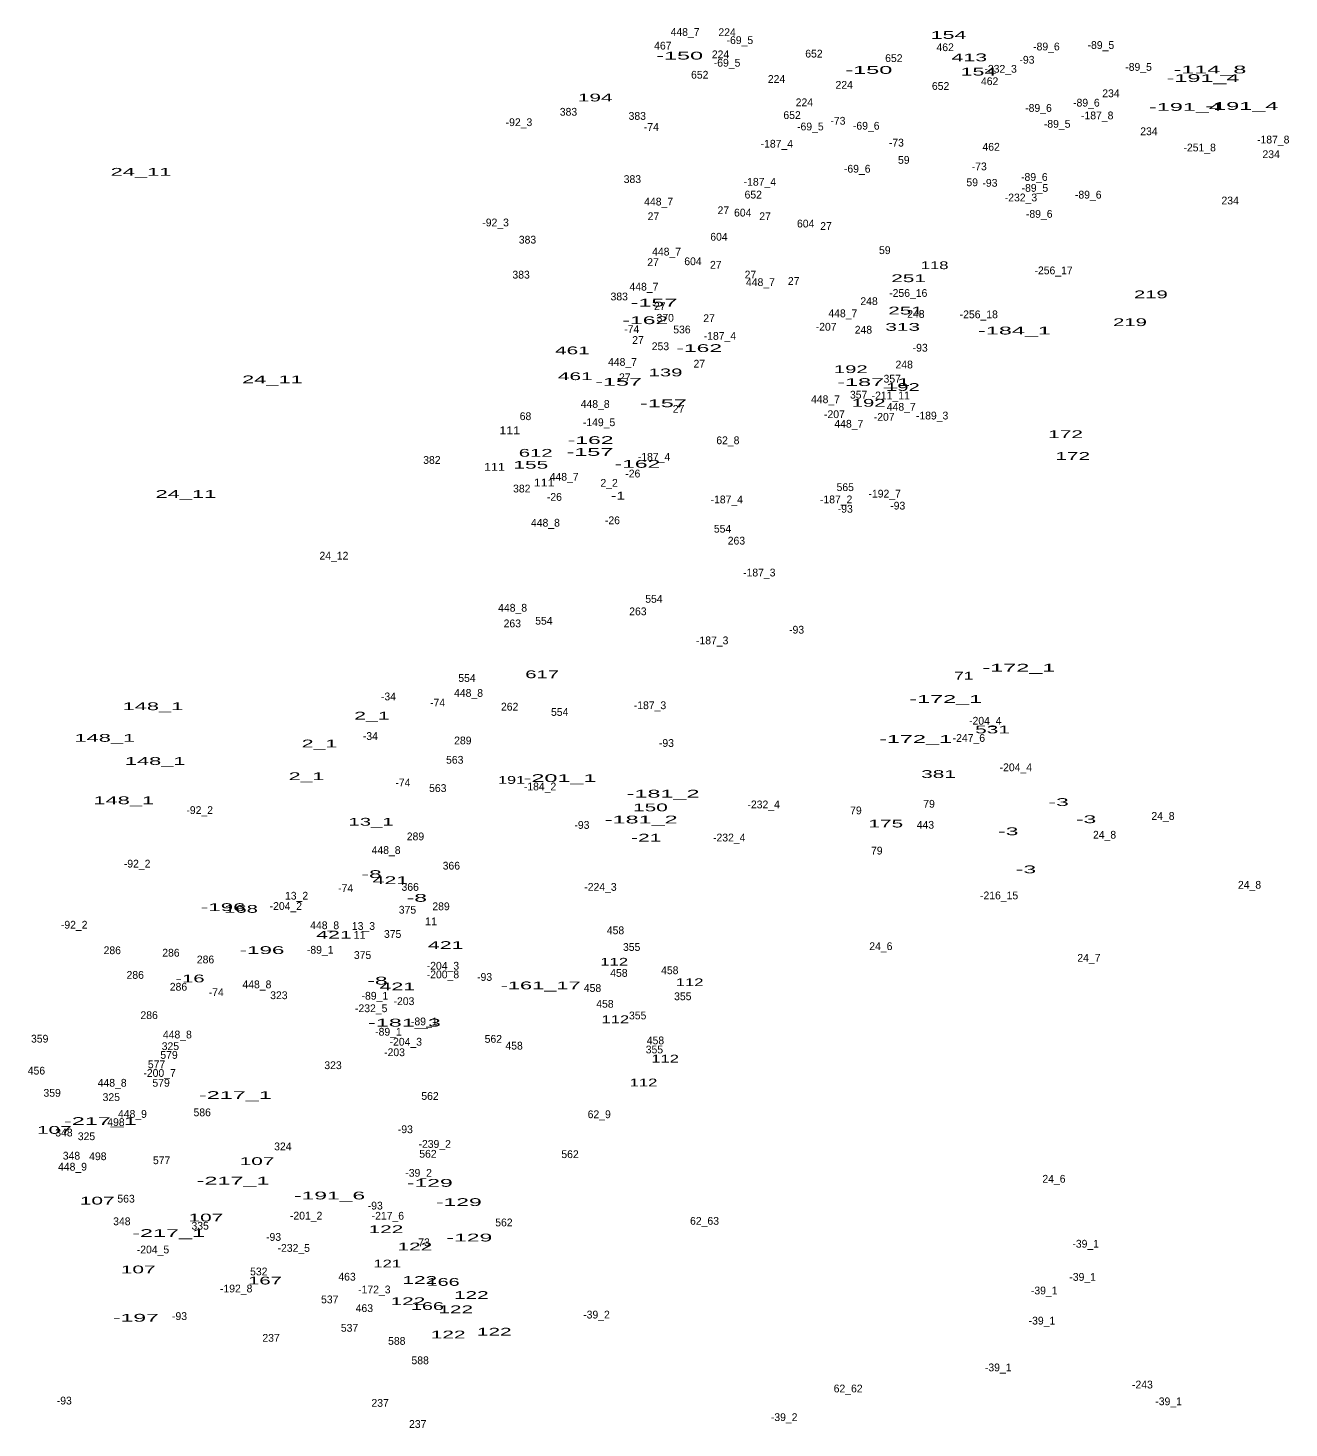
# Model space of a CAD drawing. Extents: x -661742 to -657295, y -1002932 to -996888.
# Drawn here: x -660431 to -659782, y -1001400 to -1000680 of the extents above; entities that cross this region are included whole.
import ezdxf
from ezdxf.enums import TextEntityAlignment as Align

# ---------------------------------------------------------------- set-up
doc = ezdxf.new("R2010")
doc.units = 0
doc.header["$LTSCALE"] = 1.6
doc.layers.add('24', color=7, linetype='Continuous')

msp = doc.modelspace()

# ---------------------------------------------------------------- texts
at = {"layer": '24'}
for s, p in [('448_7', (-660092.849, -1000684.01)), ('224', (-660071.231, -1000684.11)), ('467', (-660104.283, -1000691.03)), ('-69_5', (-660064.653, -1000688.2)), ('462', (-659959.067, -1000691.86)), ('-89_6', (-659906.993, -1000691.47)), ('-89_5', (-659878.978, -1000690.72)), ('224', (-660074.621, -1000695.52)), ('652', (-660026.563, -1000695.14)), ('652', (-659985.463, -1000697.45)), ('-93', (-659916.99, -1000698.3)), ('652', (-660085.303, -1000706)), ('-69_5', (-660071.243, -1000699.84)), ('-232_3', (-659930.532, -1000702.95)), ('-89_5', (-659859.588, -1000701.97)), ('224', (-660045.801, -1000708.19)), ('224', (-660010.991, -1000711.19)), ('652', (-659961.423, -1000711.8)), ('462', (-659936.187, -1000709.32)), ('224', (-660031.491, -1000720.19)), ('-89_6', (-659886.443, -1000720.36)), ('234', (-659873.791, -1000715.54)), ('383', (-660152.807, -1000725.05)), ('383', (-660117.417, -1000727.18)), ('652', (-660037.803, -1000726.75)), ('-89_6', (-659911.063, -1000723.08)), ('-187_8', (-659880.862, -1000726.93)), ('-92_3', (-660178.268, -1000730.4)), ('-74', (-660110.195, -1000732.89)), ('-69_5', (-660028.403, -1000732.62)), ('-73', (-660014.211, -1000729.68)), ('-69_6', (-659999.648, -1000732.23)), ('-89_5', (-659901.468, -1000731.25)), ('234', (-659854.261, -1000735.08)), ('-187_4', (-660045.646, -1000741.48)), ('-73', (-659984.171, -1000740.92)), ('-187_8', (-659790.322, -1000739.34)), ('59', (-659980.353, -1000749.8)), ('462', (-659935.417, -1000743.06)), ('-251_8', (-659828.156, -1000743.42)), ('234', (-659791.411, -1000746.88)), ('-69_6', (-660004.298, -1000754.34)), ('-73', (-659941.531, -1000753.14)), ('383', (-660119.937, -1000759.68)), ('-187_4', (-660054.366, -1000761.07)), ('59', (-659945.153, -1000761.31)), ('-93', (-659936.03, -1000761.61)), ('-89_6', (-659913.203, -1000758.57)), ('-89_5', (-659912.908, -1000764.2)), ('448_7', (-660106.429, -1000771.24)), ('652', (-660057.773, -1000767.66)), ('-232_3', (-659920.082, -1000769.12)), ('-89_6', (-659885.473, -1000767.68)), ('234', (-659812.491, -1000770.68)), ('27', (-660073.153, -1000775.7)), ('604', (-660063.191, -1000776.92)), ('-89_6', (-659910.683, -1000777.57)), ('-92_3', (-660190.288, -1000781.98)), ('27', (-660109.123, -1000778.79)), ('27', (-660051.683, -1000778.79)), ('604', (-660030.811, -1000782.55)), ('27', (-660020.353, -1000783.82)), ('383', (-660173.887, -1000790.83)), ('604', (-660075.401, -1000789.33)), ('448_7', (-660102.349, -1000796.98)), ('59', (-659990.113, -1000796.23)), ('27', (-660109.313, -1000802.4)), ('604', (-660088.781, -1000801.94)), ('27', (-660077.023, -1000803.75)), ('-256_17', (-659903.306, -1000806.63)), ('383', (-660177.177, -1000808.83)), ('27', (-660059.223, -1000808.78)), ('448_7', (-660054.079, -1000812.69)), ('27', (-660036.983, -1000812.07)), ('383', (-660126.707, -1000820.05)), ('448_7', (-660113.989, -1000815.02)), ('-256_16', (-659978.046, -1000818.26)), ('27', (-660105.833, -1000825.03)), ('448_7', (-660011.699, -1000828.71)), ('248', (-659998.211, -1000822.45)), ('370', (-660103.057, -1000831.02)), ('27', (-660080.503, -1000831.22)), ('-207', (-660020.284, -1000835.62)), ('248', (-659974.131, -1000829.03)), ('-256_18', (-659941.781, -1000829.25)), ('-74', (-660120.275, -1000836.84)), ('27', (-660117.053, -1000842.44)), ('536', (-660094.443, -1000837.03)), ('-187_4', (-660074.916, -1000840.32)), ('248', (-660001.111, -1000837.15)), ('253', (-660105.517, -1000845.66)), ('-93', (-659971.91, -1000846.41)), ('448_7', (-660125.019, -1000853.73)), ('27', (-660085.523, -1000854.63)), ('248', (-659980.131, -1000855.05)), ('27', (-660123.823, -1000861.6)), ('357', (-659986.303, -1000862.35)), ('357', (-660003.563, -1000870.56)), ('-211_11', (-659987.07, -1000870.97)), ('448_8', (-660139.074, -1000875.34)), ('27', (-660096.163, -1000877.85)), ('448_7', (-660020.619, -1000872.93)), ('448_7', (-659981.649, -1000876.81)), ('68', (-660174.913, -1000881.63)), ('-149_5', (-660137.076, -1000884.74)), ('-207', (-660016.014, -1000880.61)), ('448_7', (-660008.599, -1000885.53)), ('-207', (-659990.424, -1000881.97)), ('-189_3', (-659965.782, -1000881.31)), ('62_8', (-660070.82, -1000894.03)), ('382', (-660223.057, -1000904.15)), ('-187_4', (-660108.806, -1000902.53)), ('448_7', (-660155.029, -1000912.8)), ('-26', (-660119.72, -1000911.13)), ('382', (-660176.827, -1000918.85)), ('2_2', (-660131.896, -1000915.92)), ('565', (-660010.463, -1000918.14)), ('-192_7', (-659990.187, -1000921.46)), ('-26', (-660160.05, -1000923.15)), ('-187_4', (-660071.386, -1000924.44)), ('-187_2', (-660015.132, -1000924.43)), ('-93', (-660010.45, -1000929.26)), ('-93', (-659983.46, -1000927.64)), ('448_8', (-660164.664, -1000936.43)), ('-26', (-660130.19, -1000935.17)), ('554', (-660073.561, -1000939.51)), ('263', (-660066.433, -1000945.65)), ('24_12', (-660273.453, -1000953.38)), ('-187_3', (-660054.662, -1000962.05)), ('448_8', (-660181.534, -1000980.16)), ('554', (-660108.851, -1000975.59)), ('554', (-660165.461, -1000986.84)), ('263', (-660117.103, -1000982.02)), ('263', (-660181.693, -1000988.21)), ('-93', (-660035.47, -1000991.45)), ('-187_3', (-660078.892, -1000996.95)), ('554', (-660205.001, -1001016.31)), ('-34', (-660245.399, -1001025.78)), ('-74', (-660220.125, -1001028.94)), ('448_8', (-660204.214, -1001023.99)), ('-187_3', (-660110.882, -1001030.31)), ('262', (-660183.053, -1001031.04)), ('554', (-660157.311, -1001033.77)), ('-204_4', (-659938.435, -1001038.29)), ('-34', (-660254.699, -1001046.15)), ('289', (-660207.143, -1001048.42)), ('-93', (-660102.43, -1001049.75)), ('-247_6', (-659946.878, -1001047.13)), ('563', (-660211.293, -1001058.37)), ('-204_4', (-659922.725, -1001062.24)), ('-74', (-660237.955, -1001070.05)), ('563', (-660220.023, -1001072.92)), ('-184_2', (-660167.43, -1001072.08)), ('79', (-659967.348, -1001081)), ('-92_2', (-660342.478, -1001084.25)), ('-232_4', (-660052.427, -1001081.33)), ('79', (-660004.958, -1001084.39)), ('24_8', (-659847.04, -1001087.26)), ('-93', (-660145.88, -1001091.87)), ('443', (-659969.226, -1001091.81)), ('289', (-660231.513, -1001097.76)), ('-232_4', (-660070.127, -1001098.36)), ('24_8', (-659877.08, -1001096.92)), ('448_8', (-660246.614, -1001104.8)), ('79', (-659994.228, -1001105.09)), ('-92_2', (-660374.658, -1001111.79)), ('366', (-660213.038, -1001112.83)), ('366', (-660234.218, -1001123.76)), ('-224_3', (-660136.357, -1001123.76)), ('24_8', (-659802.52, -1001122.67)), ('13_2', (-660292.649, -1001128.28)), ('-74', (-660267.425, -1001124.35)), ('-216_15', (-659931.335, -1001128.13)), ('-204_2', (-660298.181, -1001133.59)), ('375', (-660235.613, -1001135.49)), ('289', (-660218.353, -1001133.74)), ('-92_2', (-660407.038, -1001143.21)), ('448_8', (-660278.214, -1001143.48)), ('13_3', (-660258.259, -1001143.85)), ('375', (-660243.243, -1001147.96)), ('458', (-660128.621, -1001146.08)), ('286', (-660387.433, -1001156.34)), ('286', (-660357.263, -1001157.6)), ('-89_1', (-660280.492, -1001156.08)), ('375', (-660258.723, -1001158.8)), ('355', (-660120.307, -1001154.66)), ('24_6', (-659992.134, -1001154.24)), ('24_7', (-659885.135, -1001160.23)), ('286', (-660339.473, -1001161.08)), ('-204_3', (-660217.391, -1001164.31)), ('458', (-660100.701, -1001166.63)), ('286', (-660375.633, -1001169.02)), ('448_8', (-660313.054, -1001173.88)), ('-200_8', (-660217.37, -1001168.76)), ('-93', (-660195.95, -1001170.07)), ('458', (-660126.871, -1001167.99)), ('286', (-660353.393, -1001175.11)), ('-74', (-660333.965, -1001177.91)), ('323', (-660301.757, -1001179.47)), ('-89_1', (-660252.382, -1001179.74)), ('458', (-660140.441, -1001175.75)), ('355', (-660094.007, -1001180.01)), ('-232_5', (-660254.272, -1001186.17)), ('-203', (-660237.419, -1001182.52)), ('458', (-660134.051, -1001183.89)), ('286', (-660368.483, -1001189.72)), ('-89_1', (-660226.982, -1001192.93)), ('355', (-660117.217, -1001189.87)), ('359', (-660424.763, -1001201.82)), ('448_8', (-660353.964, -1001199.68)), ('-89_1', (-660245.402, -1001198.26)), ('-204_3', (-660236.481, -1001203.39)), ('562', (-660191.453, -1001201.92)), ('458', (-660108.071, -1001202.71)), ('579', (-660358.258, -1001210.17)), ('325', (-660357.547, -1001205.66)), ('-203', (-660242.269, -1001208.8)), ('458', (-660180.771, -1001205.42)), ('355', (-660108.607, -1001207.38)), ('577', (-660364.679, -1001215)), ('323', (-660273.907, -1001215.46)), ('456', (-660426.447, -1001218.25)), ('448_8', (-660387.504, -1001224.5)), ('-200_7', (-660363.106, -1001219.46)), ('579', (-660362.328, -1001224.51)), ('359', (-660418.373, -1001229.68)), ('325', (-660387.947, -1001231.88)), ('562', (-660224.023, -1001231.28)), ('498', (-660385.557, -1001244.74)), ('448_9', (-660377.069, -1001240.52)), ('586', (-660341.183, -1001239.71)), ('62_9', (-660136.986, -1001240.7)), ('348', (-660412.301, -1001250.1)), ('325', (-660400.717, -1001252)), ('-93', (-660236.71, -1001248.41)), ('324', (-660299.721, -1001257.23)), ('-239_2', (-660221.608, -1001255.95)), ('562', (-660225.083, -1001261.03)), ('448_9', (-660407.899, -1001267.67)), ('348', (-660408.431, -1001262.01)), ('498', (-660394.867, -1001262.3)), ('577', (-660362.059, -1001264.35)), ('562', (-660152.003, -1001261.23)), ('-39_2', (-660229.888, -1001270.82)), ('24_6', (-659903.104, -1001273.89)), ('563', (-660380.343, -1001284.11)), ('-93', (-660252.18, -1001287.69)), ('348', (-660382.521, -1001295.76)), ('-201_2', (-660287.74, -1001292.84)), ('-217_6', (-660245.707, -1001292.91)), ('562', (-660186.023, -1001296.33)), ('62_63', (-660082.826, -1001295.53)), ('335', (-660342.247, -1001298.03)), ('-93', (-660304.48, -1001303.79)), ('-204_5', (-660366.491, -1001310.26)), ('-232_5', (-660294.112, -1001309.45)), ('73', (-660227.093, -1001306.55)), ('-39_1', (-659886.802, -1001307.29)), ('532', (-660312.087, -1001321.56)), ('463', (-660266.697, -1001324.24)), ('-39_1', (-659888.362, -1001324.35)), ('-192_8', (-660323.712, -1001330.33)), ('-172_3', (-660252.652, -1001330.81)), ('-39_1', (-659908.132, -1001331.34)), ('537', (-660275.603, -1001335.92)), ('-93', (-660352.85, -1001344.51)), ('463', (-660257.787, -1001340.41)), ('-39_2', (-660138.388, -1001343.74)), ('-39_1', (-659909.292, -1001346.85)), ('537', (-660265.423, -1001350.56)), ('237', (-660305.773, -1001355.7)), ('588', (-660241.107, -1001357.27)), ('588', (-660229.087, -1001367.26)), ('-39_1', (-659931.782, -1001370.9)), ('62_62', (-660008.966, -1001381.75)), ('-243', (-659857.609, -1001379.73)), ('-93', (-660412.12, -1001387.97)), ('237', (-660249.683, -1001389.17)), ('-39_1', (-659844.152, -1001388.35)), ('-39_2', (-660041.878, -1001396.49)), ('237', (-660230.343, -1001400.01))]:
    msp.add_text(s, height=4, dxfattribs=at).set_placement(p, align=Align.CENTER)
for s, width, p in [('154', 2.05, (-659957.333, -1000685.53)), ('-150', 2.25, (-660095.627, -1000696.17)), ('413', 2.05, (-659946.643, -1000697.07)), ('-150', 2.25, (-659998.307, -1000703.54)), ('154', 2.05, (-659941.953, -1000704.4)), ('-114_8', 2.25, (-659822.903, -1000703.3)), ('-191_4', 2.25, (-659826.458, -1000707.71)), ('194', 2, (-660139.068, -1000717.72)), ('-191_4', 2.25, (-659835.478, -1000722.55)), ('-191_4', 2.25, (-659806.488, -1000722.06)), ('24_11', 2.1, (-660372.651, -1000755.93)), ('118', 1.6, (-659964.494, -1000803.99)), ('251', 2, (-659977.867, -1000810.66)), ('219', 1.95, (-659853.273, -1000818.97)), ('-157', 2.25, (-660108.815, -1000823.22)), ('251', 2, (-659979.417, -1000827.3)), ('-162', 2.2, (-660113.295, -1000832.26)), ('313', 2, (-659980.917, -1000835.69)), ('219', 1.95, (-659864.003, -1000833.27)), ('-184_1', 2.25, (-659923.413, -1000837.57)), ('461', 2, (-660150.768, -1000847.78)), ('-162', 2.2, (-660085.575, -1000846.61)), ('192', 1.95, (-660007.613, -1000857.44)), ('24_11', 2.1, (-660305.071, -1000862.71)), ('461', 2, (-660149.318, -1000861.05)), ('-157', 2.25, (-660127.045, -1000863.94)), ('139', 1.95, (-660102.893, -1000859.11)), ('-187_1', 2.25, (-659995.833, -1000864.08)), ('192', 1.95, (-659980.833, -1000866.63)), ('-157', 2.25, (-660103.975, -1000875)), ('192', 1.95, (-659998.433, -1000874.75)), ('111', 1.2, (-660183.03, -1000888.89)), ('172', 2, (-659897.133, -1000890.88)), ('612', 1.95, (-660169.663, -1000900.47)), ('-157', 2.25, (-660141.775, -1000900.02)), ('-162', 2.2, (-660141.405, -1000893.93)), ('111', 1.2, (-660190.87, -1000907.66)), ('155', 2, (-660172.167, -1000906.62)), ('-162', 2.2, (-660117.365, -1000906.15)), ('172', 2, (-659893.463, -1000902.1)), ('24_11', 2.1, (-660349.591, -1000921.66)), ('111', 1.2, (-660165.34, -1000915.78)), ('-1', 1.55, (-660127.281, -1000922.52)), ('617', 1.95, (-660166.337, -1001014.38)), ('71', 1.65, (-659949.483, -1001015.11)), ('-172_1', 2.25, (-659921.163, -1001011)), ('-172_1', 2.25, (-659958.773, -1001027.1)), ('148_1', 2.1, (-660366.541, -1001030.83)), ('2_1', 2.05, (-660253.889, -1001035.66)), ('531', 2, (-659934.717, -1001042.76)), ('148_1', 2.1, (-660391.291, -1001047.09)), ('2_1', 2.05, (-660280.869, -1001049.98)), ('-172_1', 2.25, (-659974.283, -1001047.66)), ('148_1', 2.1, (-660365.381, -1001058.98)), ('381', 2, (-659962.487, -1001065.7)), ('2_1', 2.05, (-660287.539, -1001066.81)), ('191', 1.55, (-660182.089, -1001068.72)), ('-201_1', 2.25, (-660157.144, -1001067.79)), ('148_1', 2.1, (-660381.531, -1001079.2)), ('-181_2', 2.25, (-660104.157, -1001075.8)), ('-3', 2.2, (-659900.734, -1001080.11)), ('150', 2, (-660110.664, -1001082.85)), ('13_1', 1.95, (-660254.365, -1001090.24)), ('-181_2', 2.25, (-660115.397, -1001089.09)), ('175', 2, (-659989.583, -1001091.16)), ('-3', 2.2, (-659926.624, -1001095.15)), ('-3', 2.2, (-659886.594, -1001088.94)), ('-21', 2, (-660112.841, -1001098.43)), ('-3', 2.2, (-659917.514, -1001114.73)), ('-8', 2.2, (-660254.074, -1001117.17)), ('421', 2.05, (-660244.403, -1001120.29)), ('-8', 2.2, (-660230.814, -1001129.39)), ('-196', 2.15, (-660330.389, -1001134.15)), ('168', 1.95, (-660321.223, -1001135.06)), ('11', 1.05, (-660223.484, -1001141.47)), ('421', 2.05, (-660273.413, -1001148.34)), ('11', 1.05, (-660260.234, -1001148.44)), ('-196', 2.15, (-660310.429, -1001156.26)), ('421', 2.05, (-660215.973, -1001153.67)), ('112', 1.6, (-660129.304, -1001162.25)), ('-16', 1.95, (-660347.495, -1001170.85)), ('-8', 2.2, (-660251.074, -1001171.96)), ('-161_17', 2.1, (-660167.133, -1001174.41)), ('112', 1.6, (-660090.534, -1001172.8)), ('421', 2.05, (-660240.823, -1001174.95)), ('-181_3', 2.25, (-660237.197, -1001193.58)), ('112', 1.6, (-660128.724, -1001191.84)), ('112', 1.6, (-660103.104, -1001212.07)), ('112', 1.6, (-660114.224, -1001224.35)), ('-217_1', 2.25, (-660324.163, -1001230.83)), ('-217_1', 2.25, (-660393.563, -1001244.2)), ('107', 2, (-660417.239, -1001248.74)), ('107', 2, (-660312.989, -1001264.8)), ('-217_1', 2.25, (-660325.323, -1001274.85)), ('-191_6', 2.2, (-660275.697, -1001282.49)), ('-129', 2.2, (-660224.145, -1001275.99)), ('107', 2, (-660395.189, -1001285.12)), ('-129', 2.2, (-660209.215, -1001285.88)), ('107', 2, (-660339.299, -1001293.82)), ('-217_1', 2.25, (-660358.473, -1001301.8)), ('122', 2, (-660246.687, -1001299.82)), ('-129', 2.2, (-660203.785, -1001304.11)), ('122', 2, (-660231.797, -1001308.72)), ('121', 1.6, (-660246.014, -1001317.5)), ('107', 2, (-660374.109, -1001320.52)), ('167', 1.95, (-660308.887, -1001326.22)), ('122', 2, (-660229.287, -1001325.94)), ('166', 1.9, (-660217.267, -1001326.93)), ('122', 2, (-660235.377, -1001336.87)), ('166', 1.9, (-660225.337, -1001339.36)), ('122', 2, (-660202.787, -1001333.68)), ('-197', 2.2, (-660375.309, -1001345.37)), ('122', 2, (-660210.817, -1001341.03)), ('122', 2, (-660214.687, -1001353.99)), ('122', 2, (-660190.987, -1001352.54))]:
    msp.add_text(s, height=4, dxfattribs=dict(at, width=width)).set_placement(p, align=Align.CENTER)

doc.saveas('drawing.dxf')
